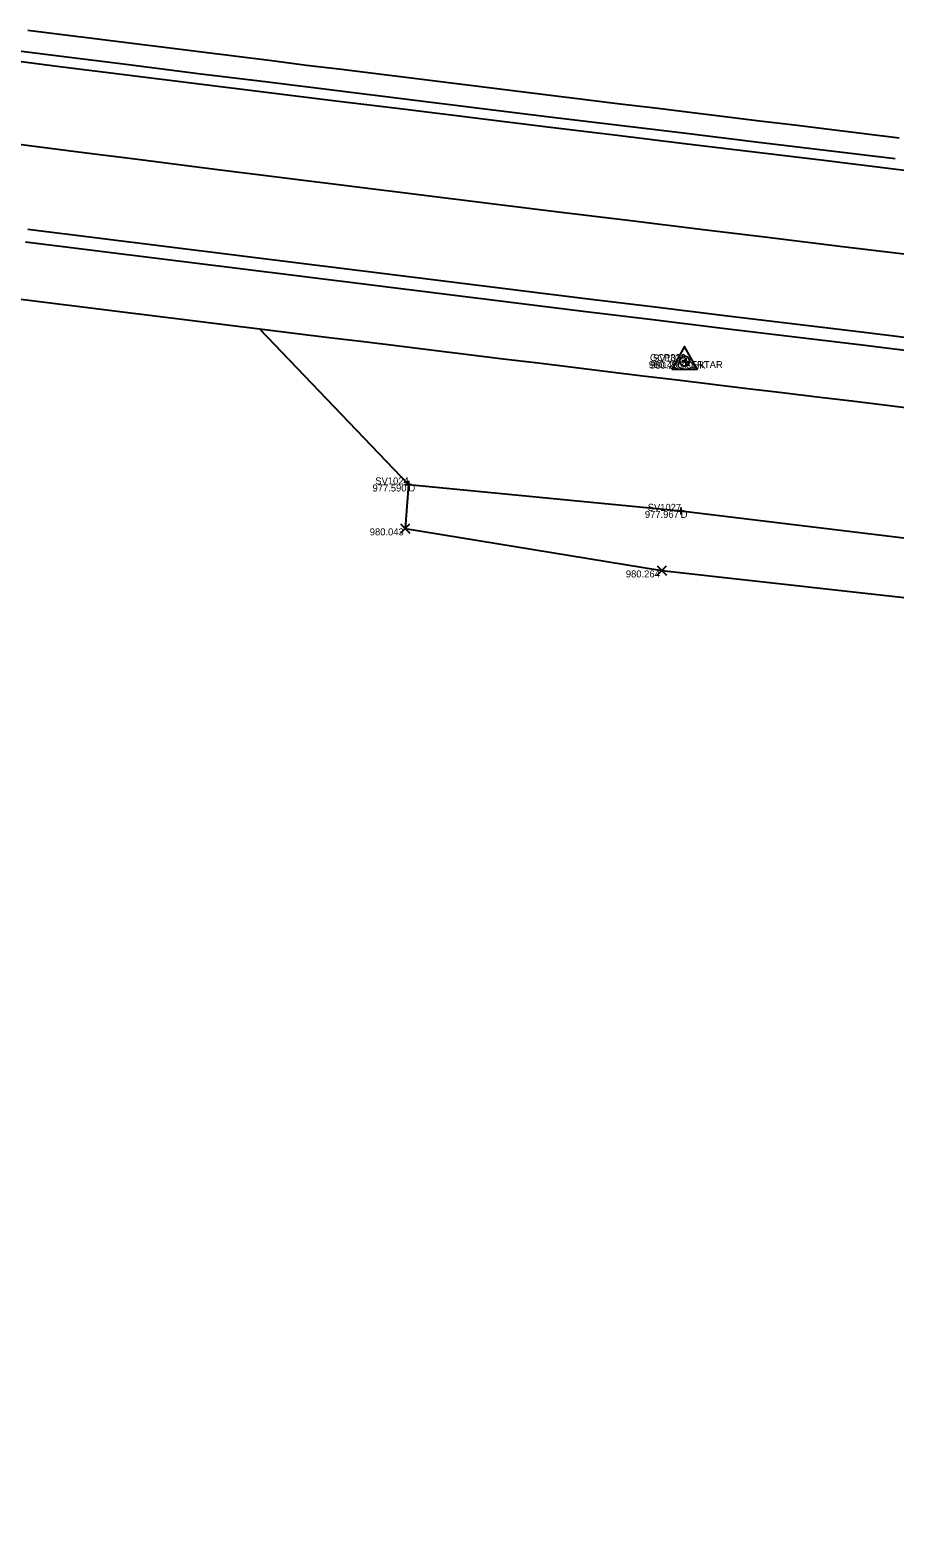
# Model space of a CAD drawing. Extents: x 2065431 to 2068157, y 709104 to 709719.
# Drawn here: x 2066854.9 to 2066978, y 709165.1 to 709379.8 of the extents above; entities that cross this region are included whole.
import ezdxf

# ---------------------------------------------------------------- set-up
doc = ezdxf.new("R2010")
doc.units = 0
for name, color, linetype in [('DT_X_Terrain_Boundary', 7, 'Continuous'), ('PM_X_Edge_Line', 7, 'Continuous'), ('PM_X_Lane_Line', 7, 'Continuous'), ('PV_X_EOP', 7, 'Continuous'), ('PV_X_Shoulder_Rumble_Strip', 7, 'Continuous'), ('RS_Raster1', 7, 'Continuous'), ('RW_X_CL_100_Bearings', 7, 'Continuous'), ('RW_X_Fee_WL', 7, 'Continuous'), ('SV_P_Aerial_Targets', 7, 'Continuous'), ('SV_X_Mon_Cells_Found', 7, 'Continuous'), ('SV_X_Text_Elevation', 7, 'Continuous'), ('SV_X_Text_Name', 7, 'Continuous')]:
    doc.layers.add(name, color=color, linetype=linetype)

msp = doc.modelspace()

# ---------------------------------------------------------------- linework, layer by layer
at = {"layer": 'DT_X_Terrain_Boundary'}
msp.add_lwpolyline([(2066852.77, 709341.57), (2066857.73, 709340.95), (2066862.69, 709340.33), (2066867.65, 709339.72), (2066872.62, 709339.1), (2066877.58, 709338.48), (2066882.54, 709337.87), (2066887.5, 709337.25), (2066908.73, 709315.06), (2066908.28, 709308.83), (2066944.81, 709302.84), (2066985.68, 709298.25), (2067022.53, 709289.45), (2067065.26, 709265.32), (2067067.67, 709234.6), (2067064.4, 709192.69), (2067102.37, 709178.61), (2067140.67, 709165.08)], dxfattribs=at)
at = {"layer": 'PM_X_Edge_Line'}
for points in [[(2066848.77, 709375.91), (2066858.69, 709374.66), (2066868.62, 709373.42), (2066878.54, 709372.19), (2066888.46, 709370.95), (2066898.39, 709369.73), (2066908.31, 709368.5), (2066918.24, 709367.28), (2066928.16, 709366.06), (2066938.09, 709364.85), (2066948.02, 709363.64), (2066957.94, 709362.44), (2066967.87, 709361.24), (2066977.8, 709360.04), (2066987.73, 709358.85)], [(2066854.54, 709351.45), (2066864.46, 709350.2), (2066874.39, 709348.96), (2066884.31, 709347.72), (2066894.23, 709346.48), (2066904.16, 709345.25), (2066914.08, 709344.03), (2066924.01, 709342.8), (2066933.93, 709341.58), (2066943.86, 709340.37), (2066953.78, 709339.16), (2066963.71, 709337.95), (2066973.64, 709336.75), (2066983.57, 709335.55)]]:
    msp.add_lwpolyline(points, dxfattribs=at)
at = {"layer": 'PM_X_Lane_Line'}
msp.add_lwpolyline([(2066851.08, 709363.81), (2066861, 709362.55), (2066870.92, 709361.29), (2066880.84, 709360.04), (2066890.76, 709358.8), (2066900.68, 709357.55), (2066910.61, 709356.32), (2066920.53, 709355.09), (2066930.46, 709353.87), (2066940.38, 709352.65), (2066950.31, 709351.44), (2066960.23, 709350.23), (2066970.16, 709349.03), (2066980.09, 709347.83)], dxfattribs=at)
at = {"layer": 'PV_X_EOP'}
for points in [[(2066854.53, 709379.77), (2066859.49, 709379.15), (2066864.45, 709378.53), (2066869.41, 709377.91), (2066874.37, 709377.29), (2066879.33, 709376.67), (2066884.3, 709376.05), (2066889.26, 709375.43), (2066894.22, 709374.81), (2066899.18, 709374.2), (2066904.14, 709373.58), (2066909.11, 709372.97), (2066914.07, 709372.35), (2066919.03, 709371.74), (2066923.99, 709371.13), (2066928.96, 709370.52), (2066933.92, 709369.91), (2066938.88, 709369.3), (2066943.84, 709368.69), (2066948.81, 709368.09), (2066953.77, 709367.48), (2066958.73, 709366.87), (2066963.7, 709366.27), (2066968.66, 709365.67), (2066973.62, 709365.06), (2066978.59, 709364.46)], [(2066852.77, 709341.57), (2066857.73, 709340.95), (2066862.69, 709340.33), (2066867.65, 709339.72), (2066872.62, 709339.1), (2066877.58, 709338.48), (2066882.54, 709337.87), (2066887.5, 709337.25), (2066892.46, 709336.64), (2066897.43, 709336.03), (2066902.39, 709335.42), (2066907.35, 709334.81), (2066912.31, 709334.2), (2066917.28, 709333.59), (2066922.24, 709332.98), (2066927.2, 709332.38), (2066932.17, 709331.77), (2066937.13, 709331.17), (2066942.09, 709330.56), (2066947.06, 709329.96), (2066952.02, 709329.36), (2066956.99, 709328.76), (2066961.95, 709328.16), (2066966.91, 709327.56), (2066971.88, 709326.97), (2066976.84, 709326.37), (2066981.81, 709325.77)]]:
    msp.add_lwpolyline(points, dxfattribs=at)
at = {"layer": 'PV_X_Shoulder_Rumble_Strip'}
for points in [[(2066849.02, 709377.34), (2066858.95, 709376.1), (2066868.87, 709374.86), (2066878.79, 709373.62), (2066888.72, 709372.39), (2066898.64, 709371.17), (2066908.57, 709369.94), (2066918.49, 709368.72), (2066928.42, 709367.5), (2066938.34, 709366.29), (2066948.27, 709365.08), (2066958.2, 709363.88), (2066968.12, 709362.68), (2066978.05, 709361.48)], [(2066854.22, 709349.64), (2066864.14, 709348.39), (2066874.06, 709347.15), (2066883.99, 709345.91), (2066893.91, 709344.68), (2066903.83, 709343.45), (2066913.76, 709342.22), (2066923.68, 709341), (2066933.61, 709339.78), (2066943.54, 709338.56), (2066953.46, 709337.35), (2066963.39, 709336.14), (2066973.32, 709334.94), (2066983.24, 709333.74)]]:
    msp.add_lwpolyline(points, dxfattribs=at)
at = {"layer": 'RS_Raster1'}
for p, q in [((2066947.72, 709332.58), (2066948.72, 709332.58)), ((2066948.22, 709333.08), (2066948.22, 709332.08)), ((2066948.22, 709332.58), (2066948.22, 709332.58)), ((2066908.23, 709315.08), (2066909.23, 709315.08)), ((2066908.73, 709315.58), (2066908.73, 709314.58)), ((2066908.73, 709315.08), (2066908.73, 709315.08)), ((2066947, 709311.32), (2066948, 709311.32)), ((2066947.5, 709311.82), (2066947.5, 709310.82)), ((2066947.5, 709311.32), (2066947.5, 709311.32))]:
    msp.add_line(p, q, dxfattribs=at)
at = {"layer": 'RW_X_CL_100_Bearings'}
for p, q in [((2066907.62, 709308.16), (2066908.95, 709309.49)), ((2066907.62, 709309.49), (2066908.95, 709308.16)), ((2066944.14, 709302.18), (2066945.48, 709303.51)), ((2066944.14, 709303.51), (2066945.48, 709302.18))]:
    msp.add_line(p, q, dxfattribs=at)
at = {"layer": 'RW_X_Fee_WL'}
msp.add_lwpolyline([(2066908.73, 709315.08), (2066947.5, 709311.32), (2066985.9, 709306.66), (2067026.26, 709300.33)], dxfattribs=at)
at = {"layer": 'SV_P_Aerial_Targets'}
msp.add_lwpolyline([(2066946.26, 709331.49), (2066949.86, 709331.49), (2066948.06, 709334.71)], close=True, dxfattribs=at)
for radius in [0.7, 0.16]:
    msp.add_circle((2066948.06, 709332.64), radius, dxfattribs=at)

# ---------------------------------------------------------------- texts
at = {"layer": 'SV_X_Mon_Cells_Found'}
for s, p in [('GCP339', (2066943.12, 709332.64)), ('SV1023', (2066943.56, 709332.58)), ('SV1024', (2066904.01, 709315.08)), ('SV1027', (2066942.8, 709311.32))]:
    msp.add_text(s, height=1, dxfattribs=at).set_placement(p)
at = {"layer": 'SV_X_Text_Elevation'}
for s, p in [('AERTAR', (2066948.06, 709331.64)), ('CHK', (2066948.22, 709331.58)), ('D', (2066908.73, 709314.08)), ('D', (2066947.5, 709310.32))]:
    msp.add_text(s, height=1, dxfattribs=at).set_placement(p)
at = {"layer": 'SV_X_Text_Name'}
for s, p in [('980.406', (2066942.95, 709331.64)), ('980.283', (2066943.16, 709331.58)), ('977.590', (2066903.62, 709314.08)), ('977.967', (2066942.4, 709310.32)), ('980.043', (2066903.22, 709307.83)), ('980.264', (2066939.69, 709301.84))]:
    msp.add_text(s, height=1, dxfattribs=at).set_placement(p)

doc.saveas('drawing.dxf')
